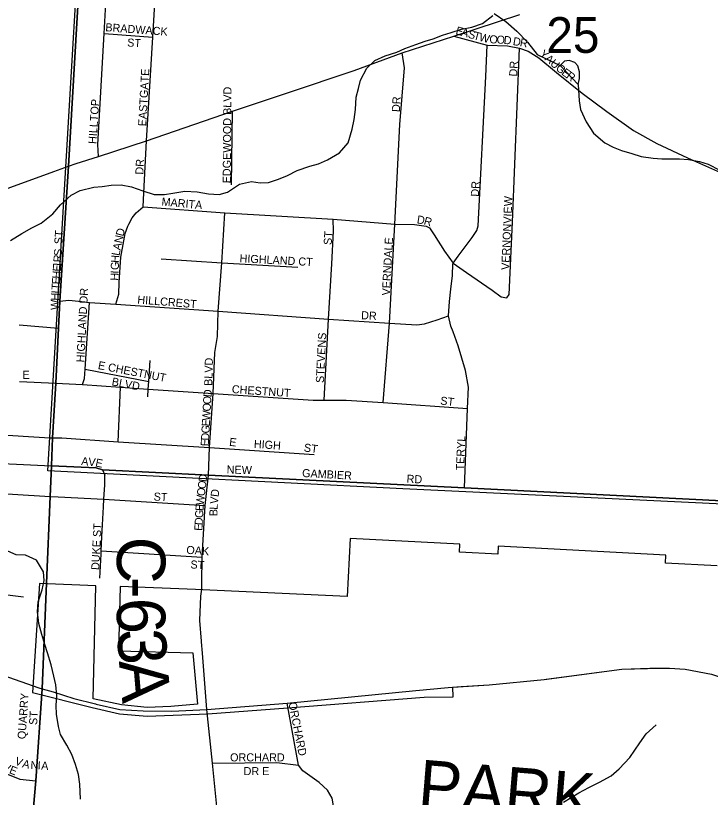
# Model space of a CAD drawing. Extents: x 1759416 to 2214760, y 252598 to 1116833.
# Drawn here: x 1977371 to 1981672, y 869319 to 874156 of the extents above; entities that cross this region are included whole.
import ezdxf

# ---------------------------------------------------------------- set-up
doc = ezdxf.new("R2010")
doc.units = 0
for name, color, linetype in [('GM_X_City_Street', 7, 'Continuous'), ('GM_X_City_Street_Text', 7, 'Continuous'), ('GM_X_Corporation', 7, 'Continuous'), ('GM_X_County_Road', 7, 'Continuous'), ('GM_X_County_Road_Text', 7, 'Continuous'), ('GM_X_Minor_Lake', 7, 'Continuous'), ('GM_X_Minor_River', 7, 'Continuous'), ('GM_X_Section', 7, 'Continuous'), ('GM_X_Section_Text', 7, 'Continuous'), ('GM_X_State_Route', 7, 'Continuous'), ('GM_X_Township', 7, 'Continuous'), ('GM_X_Township_Road_Text', 7, 'Continuous'), ('GM_X_US_Route', 7, 'Continuous')]:
    doc.layers.add(name, color=color, linetype=linetype)

msp = doc.modelspace()

# ---------------------------------------------------------------- linework, layer by layer
at = {"layer": 'GM_X_City_Street'}
for points in [[(1977883, 873285), (1977878.9, 873357.5), (1977919.3, 874044.4), (1977966.1, 874900.7), (1978005.9, 875593.5)], [(1978180.9, 873380.4), (1978219.7, 874022.9), (1978248.1, 874509.8), (1978265.8, 874818.7), (1978265.8, 874849.5), (1978246.6, 874875.1)], [(1977919.3, 874044.4), (1978219.7, 874022.9)], [(1980083.9, 874029.5), (1980290.1, 873973.8), (1980415.7, 873969.1), (1980490.1, 873955.1)], [(1980078.3, 872619.4), (1980078.5, 872624.8), (1980110.8, 872667.6), (1980196.3, 872782.9), (1980226.1, 872825.7), (1980235.2, 872854.2), (1980282.6, 873779.6), (1980290.1, 873973.8)], [(1980426.9, 872430.4), (1980447.7, 872877.6), (1980490.1, 873955.1)], [(1980490.1, 873955.1), (1980542.9, 873936.5), (1980609.6, 873894.6), (1980719.7, 873804.6), (1980877.9, 873675.8), (1981031.5, 873562.6), (1981195.9, 873444.6), (1981340.2, 873365.5), (1981530.3, 873275.4), (1981716.3, 873192.9), (1981913, 873117.8), (1982134.7, 873057.1), (1982427.2, 872997.4), (1982786.1, 872931.2), (1983154.2, 872866.4), (1983249.7, 872854.1), (1983411.4, 872851), (1984508.3, 872822.4), (1985169.3, 872863.1), (1985888.8, 872856.3)], [(1979647, 871762.4), (1979684.9, 872253.6), (1979718.7, 872865.9), (1979749.8, 873483), (1979778.4, 873832.3), (1979763.3, 873925.6)], [(1978707.4, 873109.6), (1978714.1, 873565.7)], [(1977990.8, 872370.2), (1978009.5, 872431.9), (1978011.3, 872504.9), (1978022.5, 872660.8), (1978041.3, 872762.8), (1978049.4, 872808.5), (1978065.4, 872852.7), (1978070.8, 872866.2), (1978092.3, 872905.1), (1978117.8, 872936), (1978160.7, 872973.5), (1978165, 873060.1), (1978180.9, 873380.4)], [(1978160.7, 872973.5), (1978665.3, 872936), (1979337.2, 872895.9), (1979718.7, 872865.9), (1979840, 872863.3), (1979911.3, 872852.9), (1979932, 872842.5), (1979961.8, 872799.8), (1980026.6, 872697.4), (1980078.5, 872624.8), (1980162.6, 872566.5), (1980320.7, 872456.4), (1980376.4, 872414.9), (1980412.7, 872409.7), (1980426.9, 872430.4)], [(1978570.1, 871483.2), (1978592.7, 871816.9), (1978603.2, 872070.8), (1978619.4, 872170.3), (1978624.7, 872327.2), (1978647.2, 872626.5), (1978665.3, 872936)], [(1979280.6, 871777.3), (1979308.6, 872277.1), (1979327.9, 872619), (1979339.1, 872822.9), (1979337.2, 872895.9)], [(1977617, 871848.4), (1977618.8, 871881.1), (1977637, 872221.2), (1977644.7, 872388.6), (1977673.5, 872806.1)], [(1978272.1, 872651.7), (1978647.2, 872626.5), (1979116.9, 872599.2)], [(1980149.3, 871233.5), (1980168.2, 871724.1), (1980174.6, 871856.1), (1980155.5, 871960.4), (1980110.8, 872113.6), (1980078.8, 872198.7), (1980065.5, 872233.4), (1980051.2, 872298.2), (1980057.7, 872386.3), (1980065.5, 872464.1), (1980075.9, 872548.4), (1980078.3, 872619.4)], [(1977644.7, 872388.6), (1977700.4, 872394.4), (1977798.3, 872384)], [(1977784.6, 871872.8), (1977797.1, 871910.2), (1977800.7, 871967.4), (1977827.4, 872380.9)], [(1977798.3, 872384), (1977827.4, 872380.9), (1977990.8, 872370.2), (1978624.7, 872327.2), (1979308.6, 872277.1), (1979684.9, 872253.6), (1979853.7, 872242.8)], [(1979853.7, 872242.8), (1979855, 872242.7), (1979902, 872248.2), (1979979.8, 872273.5), (1980051.2, 872298.2)], [(1977392.1, 872242.2), (1977637, 872221.2)], [(1978188.7, 871797.8), (1978192, 871844.7), (1978195.3, 871892.5), (1978204.3, 872022.6)], [(1977800.7, 871967.4), (1978195.3, 871892.5)], [(1977393.9, 871892.4), (1977618.8, 871881.1), (1977784.6, 871872.8), (1978020.1, 871856.7), (1978192, 871844.7), (1978592.7, 871816.9), (1979212.7, 871777.3), (1979280.6, 871777.3), (1979416.3, 871775.4), (1979647, 871762.4), (1980168.2, 871724.1)], [(1977591.8, 871369.4), (1977599.9, 871542.5), (1977617, 871848.4)], [(1978005.9, 871519.4), (1978020.1, 871856.7)], [(1977219.2, 871566.5), (1977582.9, 871543.6)], [(1977582.9, 871543.6), (1977599.9, 871542.5), (1977656.2, 871542.5), (1978005.9, 871519.4), (1978570.1, 871483.2)], [(1976619.5, 871518), (1976724.4, 871498.3), (1976774.7, 871474.1), (1976921.6, 871431.8), (1976994.1, 871409.7), (1977068.6, 871395.6), (1977591.8, 871369.4), (1977869, 871356.9), (1977908.6, 871345.6), (1977923.7, 871311.6)], [(1978523.1, 870646.6), (1978526.1, 870804.9), (1978544.2, 871124.9), (1978564.3, 871312.8), (1978570.1, 871483.2)], [(1978570.1, 871483.2), (1979218.4, 871439.8)], [(1977914, 871116.1), (1977916.5, 871163.1), (1977923.7, 871253.2), (1977923.7, 871311.6)], [(1978564.3, 871312.8), (1980149.3, 871233.5), (1983790.8, 871051.3)], [(1976928.4, 871220.2), (1976948.8, 871218.5), (1977584.2, 871181.1), (1977634.1, 871178.2), (1977916.5, 871163.1), (1978544.2, 871124.9)], [(1977899.7, 870822.5), (1977900.7, 870843.7), (1977904.4, 870930.4), (1977914, 871116.1)], [(1977892.2, 870675.8), (1977899.7, 870822.5)], [(1977900.7, 870843.7), (1978526.1, 870804.9)], [(1976277.6, 870626), (1976567.9, 870618.1), (1976914.7, 870593), (1977235.6, 870582.2), (1977420, 870560)], [(1977468.9, 869117.6), (1977495.1, 869420.8), (1977534.2, 869990.2)], [(1979348.7, 869164), (1979338, 869267.1), (1979330.5, 869314), (1979301.7, 869362.5), (1979250.5, 869411), (1979148.7, 869482.9), (1979121.7, 869517.3), (1979051.4, 869902.1)], [(1978680.1, 868628.4), (1978664.6, 868852.9), (1978623.1, 869200.4), (1978589.8, 869530.7), (1978554.4, 869863)], [(1977087.7, 869535.3), (1977148.1, 869530.7), (1977397.6, 869431.1), (1977495.1, 869420.8)], [(1978589.8, 869530.7), (1978988.5, 869533.8), (1979121.7, 869517.3)]]:
    msp.add_lwpolyline(points, dxfattribs=at)
at = {"layer": 'GM_X_Corporation'}
msp.add_lwpolyline([(1981713.8, 870751.3), (1981394.2, 870768), (1981396.8, 870817.9), (1980358.2, 870872.4), (1980355.6, 870822.5), (1980118.5, 870835), (1980121.1, 870884.9), (1979442, 870920.5), (1979423.2, 870561), (1978484.5, 870605.6), (1978017.3, 870622.8), (1978007.8, 870225), (1978466.9, 870213.1), (1978496.1, 869894.8), (1978330.8, 869881), (1978184.7, 869874.8), (1978026.4, 869891.8), (1977850.6, 869927.4), (1977867.4, 870628.3), (1977518.8, 870641.2), (1977476, 869966.8), (1977843.7, 869875.1), (1978014.5, 869834.7), (1978185.4, 869820.7), (1978561.2, 869834.7), (1979056.4, 869873.4), (1979899.5, 869938.3), (1980080.4, 869941.4), (1980076.8, 870001.1), (1980301.7, 870014.2), (1980642.8, 870048), (1981124, 870112.4), (1981297.7, 870117.2), (1981418.4, 870118.8), (1981515, 870112.4), (1981677.8, 870080.2)], dxfattribs=at)
at = {"layer": 'GM_X_County_Road'}
for points in [[(1978522, 870280.8), (1978521.7, 870284.3), (1978510.4, 870413), (1978517.2, 870564.1), (1978522.4, 870607.3), (1978523.1, 870646.6)], [(1978554.4, 869863), (1978527.3, 870211.6), (1978522, 870280.8)]]:
    msp.add_lwpolyline(points, dxfattribs=at)
at = {"layer": 'GM_X_Minor_Lake'}
for points in [[(1980853.6, 873730.6), (1980861.8, 873766.6), (1980862.1, 873808.6), (1980850.3, 873844.8), (1980832.4, 873864.9), (1980798.4, 873877.2), (1980768.4, 873873.3), (1980742.2, 873847.5)], [(1980742.2, 873847.5), (1980853.6, 873730.6)]]:
    msp.add_lwpolyline(points, dxfattribs=at)
at = {"layer": 'GM_X_Minor_River'}
for points in [[(1977338.1, 872765.4), (1977408.5, 872807.1), (1977470.8, 872842.7), (1977529, 872872.4), (1977601.4, 872930), (1977647.8, 872985.8), (1977714.3, 873045.5), (1977770.5, 873073.2), (1977854.7, 873094.7), (1977906.8, 873098.3), (1977962.9, 873106), (1978025, 873109.6), (1978088.9, 873097.2), (1978158.8, 873070.7), (1978228.8, 873048.2), (1978292.8, 873049.8), (1978342.9, 873057.5), (1978419.1, 873069), (1978495.1, 873066.5), (1978565.1, 873054.1), (1978631.2, 873049.7), (1978681.3, 873063.4), (1978755.7, 873113), (1978831.8, 873128.5), (1978883.9, 873122.2), (1978935.9, 873123.8), (1978998.1, 873143.5), (1979054.3, 873167.2), (1979114.5, 873196.8), (1979192.8, 873224.3), (1979244.9, 873238), (1979301.1, 873263.7), (1979375.5, 873307.3), (1979429.9, 873369.1), (1979454.5, 873453), (1979466.9, 873513.1), (1979475.3, 873575.1), (1979479.8, 873651.2), (1979494.1, 873705.2), (1979506.5, 873757.2), (1979545, 873831.1), (1979595.3, 873878.8), (1979657.5, 873906.5), (1979729.8, 873930), (1979780, 873951.8), (1979848.2, 873977.4), (1979906.4, 873997), (1979956.5, 874012.7), (1980012.7, 874034.4), (1980066.9, 874052.1), (1980131, 874071.7), (1980195.2, 874085.3), (1980261.4, 874106.9), (1980325.8, 874156.6)], [(1980333.2, 874169.5), (1980405.6, 874120), (1980473.3, 874059.5), (1980538.9, 873991), (1980598.5, 873914.5), (1980742.5, 873847.8)], [(1980853.6, 873730.6), (1980858.9, 873628.4), (1980868.6, 873574.2), (1980902.1, 873497.9), (1980947.7, 873429.5), (1981017.4, 873368.9), (1981069.3, 873342.6), (1981121.2, 873322.2), (1981185.2, 873301.8), (1981243.1, 873283.4), (1981317.1, 873272.9), (1981371.1, 873270.5), (1981481.2, 873269.8), (1981537.3, 873265.5), (1981605.2, 873253), (1981657.2, 873236.7), (1981731, 873200.1)], [(1977772.7, 869307.2), (1977767.2, 869399.4), (1977759.6, 869459.5), (1977742, 869521.7), (1977718.4, 869584), (1977686.7, 869642.3), (1977649.1, 869706.6), (1977635.4, 869756.8), (1977623.9, 869833), (1977622.2, 869887.1), (1977626.6, 869949.1), (1977619, 870015.3), (1977607.3, 870069.5), (1977589.8, 870137.7), (1977568.2, 870211.9), (1977550.5, 870264.1), (1977532.9, 870326.3), (1977515.3, 870394.6), (1977505.8, 870466.7), (1977510.2, 870528.8), (1977534.6, 870602.8), (1977547, 870660.8), (1977543.4, 870714.9), (1977499.8, 870785.3), (1977431.9, 870817.8), (1977373.9, 870820.1), (1977304, 870850.6)], [(1980762.6, 869287.9), (1980857.8, 869345.6), (1980920.1, 869379.3), (1980986.4, 869412.9), (1981056.7, 869452.5), (1981107, 869494.2), (1981173.5, 869565.9), (1981236.1, 869655.7), (1981274.5, 869711.5), (1981336.9, 869767.2)]]:
    msp.add_lwpolyline(points, dxfattribs=at)
at = {"layer": 'GM_X_Section'}
msp.add_lwpolyline([(1983297.5, 876521), (1983041.3, 871071.1), (1980762.8, 871180), (1979768.8, 871227.4), (1977569.5, 871339.3), (1977893.7, 876803.2)], close=True, dxfattribs=at)
at = {"layer": 'GM_X_State_Route'}
for points in [[(1972869.6, 871157.2), (1973322.3, 871123.7), (1973630.8, 871099.6), (1973977.1, 871084.7), (1974317.9, 871056.2), (1974634.9, 870951.4), (1974972, 870847.6), (1975249.9, 870755), (1975624.1, 870620.3), (1975663.6, 870608), (1975882.4, 870537.8), (1976011.8, 870498.1), (1976209.2, 870436.6), (1976578.2, 870317.4), (1976616.7, 870304.5), (1976887.8, 870217.1), (1977109.7, 870135.7), (1977212, 870101.6), (1977513.8, 869997.3)], [(1980655, 870049.6), (1981124, 870112.4), (1981283.4, 870116.8)], [(1981283.4, 870116.8), (1981297.7, 870117.2), (1981418.4, 870118.8), (1981515, 870112.4), (1981677.8, 870080.2), (1981849.4, 870025.6), (1982015.3, 869935.8), (1982097.2, 869879.3), (1982122.9, 869863)], [(1980129.8, 870004.2), (1980301.7, 870014.2), (1980642.8, 870048), (1980655, 870049.6)], [(1977513.8, 869997.3), (1977534.2, 869990.2), (1977602.8, 869970.9), (1977731.1, 869930.4), (1977864.6, 869897.1), (1977870.2, 869895.8)], [(1978554.4, 869863), (1978554.4, 869863), (1979051.4, 869902.1), (1979849.2, 869980), (1980048.3, 869999.4), (1980129.8, 870004.2)], [(1977870.2, 869895.8), (1978015.3, 869863), (1978159.7, 869853.9), (1978336.7, 869851.7), (1978554.4, 869863)]]:
    msp.add_lwpolyline(points, dxfattribs=at)
at = {"layer": 'GM_X_Township'}
for points in [[(1983790.8, 871051.3), (1980149.3, 871233.5), (1978564.3, 871312.8), (1977908.6, 871345.6), (1977869, 871356.9), (1977591.8, 871369.4), (1977599.9, 871542.6), (1977618.8, 871881.1), (1977637, 872221.2), (1977644.7, 872388.6), (1977697.3, 873223.6), (1977838.2, 875632.9), (1977979.1, 878190.1), (1978022.2, 878973.2), (1978052.6, 879525.8), (1978080.8, 880037.7), (1978275, 883589.5), (1978647.5, 890098.7)], [(1956242.2, 879260.7), (1964932.8, 878929.4), (1964958.6, 878928.7), (1965060.6, 878925.7), (1965111.4, 878913), (1968980.9, 878660), (1969836.3, 878615.3), (1971368.2, 878535.3), (1971697.9, 878518.1), (1976487.6, 878268), (1977255.6, 878227.9), (1977979.1, 878190.1), (1977838.2, 875632.9), (1977697.3, 873223.6), (1977644.7, 872388.6), (1977637, 872221.2), (1977618.8, 871881.1), (1977599.9, 871542.6), (1977591.8, 871369.4), (1977584.2, 871181.1), (1977562.4, 870644.2), (1977534.2, 869990.2), (1977495.1, 869420.8), (1977468.9, 869117.6)], [(1977468.9, 869117.6), (1977495.1, 869420.8), (1977534.2, 869990.2), (1977562.4, 870644.2), (1977584.2, 871181.1), (1977591.8, 871369.4), (1977869, 871356.9), (1977908.6, 871345.6), (1978564.3, 871312.8), (1980149.3, 871233.5), (1983790.8, 871051.3)]]:
    msp.add_lwpolyline(points, dxfattribs=at)
at = {"layer": 'GM_X_US_Route'}
for points in [[(1979053, 873678.3), (1979466.8, 873815.7), (1979763.3, 873925.6), (1980083.9, 874029.5), (1980491.8, 874162)], [(1977607.9, 873191.4), (1977697.3, 873223.6), (1977744.7, 873240.7), (1977883, 873285), (1978180.9, 873380.4), (1978714.1, 873565.7), (1979053, 873678.3)], [(1977044.2, 872988.4), (1977072.2, 872998.2), (1977607.9, 873191.4)]]:
    msp.add_lwpolyline(points, dxfattribs=at)

# ---------------------------------------------------------------- texts
at = {"layer": 'GM_X_City_Street_Text'}
for s, rotation, p in [('BRADWACK', 355.7633, (1977924.7, 874059.8)), ('E', 344.3136, (1980091.4, 874041.9)), ('A', 344.3098, (1980125.2, 874032.4)), ('S', 344.3136, (1980167.6, 874020.5)), ('T', 344.3136, (1980201.5, 874011)), ('W', 345.8348, (1980236.8, 874001.1)), ('ST', 356.4254, (1978060, 873965.2)), ('O', 356.829, (1980302.6, 873985.5)), ('O', 357.7748, (1980347.4, 873983)), ('D', 354.2851, (1980390.6, 873981.4)), ('D', 349.6502, (1980446.3, 873974.8)), ('R', 349.4997, (1980489.5, 873966.9)), ('Y', 318.5571, (1980609.8, 873912.3)), ('A', 318.5571, (1980642.8, 873883.2)), ('DR', 86.989, (1980475.4, 873778.1)), ('U', 318.5407, (1980675.8, 873854.1)), ('EASTGATE', 86.8218, (1978178.6, 873470.2)), ('G', 321.121, (1980710.6, 873823.3)), ('E', 323.0551, (1980746.4, 873794.6)), ('R', 323.1312, (1980774.6, 873773.4)), ('EDGEWOOD BLVD', 89.5306, (1978702.2, 873117.7)), ('HILLTOP', 86.1237, (1977870.6, 873360.3)), ('DR', 86.989, (1979749.4, 873558.2)), ('DR', 86.989, (1978161, 873170.9)), ('DR', 86.9884, (1980238.4, 873034.5)), ('VERNONVIEW', 87.5869, (1980427, 872581.3)), ('MARITA', 354.8041, (1978272.4, 872981.2)), ('D', 350.7569, (1979852.1, 872871.2)), ('R', 344.0613, (1979894.1, 872864.5)), ('D', 75.757, (1978037.7, 872786.9)), ('ST', 86.1879, (1977659.4, 872739.9)), ('N', 78.0472, (1978028.7, 872744.3)), ('ST', 86.4118, (1979327, 872735.4)), ('A', 78.1113, (1978019.7, 872701.3)), ('VERNDALE', 86.9459, (1979687.8, 872423)), ('S', 86.0888, (1977656.5, 872667.4)), ('L', 79.7831, (1978013.5, 872667)), ('R', 86.0632, (1977653.8, 872627.9)), ('H', 85.8209, (1978010.5, 872624.5)), ('HIGHLAND CT', 356.9866, (1978756.1, 872629.8)), ('E', 86.0623, (1977649.9, 872570.8)), ('I', 86.1025, (1977652.3, 872605.9)), ('G', 88.1575, (1978009.1, 872581.1)), ('H', 86.0857, (1977646.9, 872526.9)), ('H', 88.1637, (1978007, 872515.1)), ('I', 88.1589, (1978008.4, 872559.1)), ('E', 86.0888, (1977644.5, 872491.8)), ('T', 86.0623, (1977642.1, 872456.6)), ('HIGHLAND DR', 87.0179, (1977795.8, 872009.3)), ('H', 86.6104, (1977638, 872390.9)), ('I', 86.1074, (1977640.6, 872434.7)), ('HILLCREST', 355.4255, (1978122.7, 872374.6)), ('W', 89.3443, (1977637.4, 872334.3)), ('DR', 356.989, (1979508.5, 872277.8)), ('STEVENS', 87.186, (1979278.6, 871881.7)), ('E CHESTNUT', 349.0871, (1977877.4, 871969.7)), ('BLVD', 88.4935, (1978587.8, 871863.9)), ('E', 0, (1977413.6, 871908.3)), ('BLVD', 349.2866, (1977962.7, 871868.5)), ('D', 84.3307, (1978582.6, 871792.7)), ('CHESTNUT', 356.0808, (1978707.8, 871820.3)), ('O', 86.8068, (1978580.2, 871749.4)), ('ST', 352.8783, (1979997.5, 871749.8)), ('O', 86.829, (1978577.8, 871705.5)), ('W', 86.8043, (1978574.6, 871648.3)), ('E', 86.8216, (1978572.6, 871613.2)), ('G', 86.8068, (1978570.2, 871569.2)), ('E', 86.802, (1978565.8, 871490.1)), ('D', 86.829, (1978567.7, 871525.3)), ('E', 352.8783, (1978690.7, 871494.6)), ('TERYL', 87.4567, (1980146, 871340.4)), ('HIGH', 356.1833, (1978844.2, 871481.4)), ('ST', 352.4111, (1979152.8, 871459.4)), ('A', 354.1763, (1977775.1, 871375.8)), ('V', 354.1804, (1977818.8, 871371.4)), ('E', 348.39, (1977861.3, 871367.1)), ('NEW', 358.2109, (1978676.7, 871323)), ('GAMBIER', 356.9047, (1979143.3, 871301.1)), ('D', 83.1408, (1978552, 871268.1)), ('RD', 356.9776, (1979790.1, 871265.8)), ('O', 83.1433, (1978546.7, 871224.4)), ('ST', 356.4254, (1978223.8, 871155.8)), ('O', 83.165, (1978541.5, 871180.7)), ('D', 83.2978, (1978626.8, 871175.4)), ('W', 83.8009, (1978535.3, 871124)), ('V', 84.4177, (1978622.6, 871131.9)), ('E', 86.2277, (1978533.1, 871089.4)), ('B', 89.4657, (1978620, 871058.3)), ('L', 86.364, (1978620.4, 871097.2)), ('G', 86.784, (1978530.6, 871045.6)), ('DUKE ST', 87.0365, (1977888.1, 870724.2)), ('E', 86.802, (1978526.2, 870966.6)), ('D', 86.785, (1978528.1, 871001.7)), ('OAK', 356.1879, (1978426.2, 870825.8)), ('ST', 356.4254, (1978451.6, 870735.6)), ('QUARRY', 86.1198, (1977431.9, 869677.1)), ('ORCHARD', 281.1436, (1979059.6, 869903.1)), ('ST', 86.4254, (1977503.2, 869765.3)), ('V', 339.0143, (1977360.8, 869523.3)), ('ORCHARD', 0, (1978698.4, 869541.1)), ('AVE', 337.838, (1977244.5, 869503.7)), ('A', 346.6065, (1977408.8, 869505.4)), ('N', 357.6623, (1977462, 869493.7)), ('I', 356.8517, (1977505.8, 869491.9)), ('A', 356.8068, (1977527.8, 869490.7)), ('DR E', 0, (1978782, 869456))]:
    msp.add_text(s, height=50, rotation=rotation, dxfattribs=at).set_placement(p)
at = {"layer": 'GM_X_County_Road_Text'}
for s, rotation, p in [('C', 268.6377, (1978001.3, 870935.4)), ('-', 269.5633, (1977995.4, 870683.8)), ('6', 271.4066, (1977994.5, 870550)), ('3', 273.0064, (1977999.4, 870356.1)), ('A', 274.7777, (1978009.8, 870161.5))]:
    msp.add_text(s, height=300, rotation=rotation, dxfattribs=at).set_placement(p)
at = {"layer": 'GM_X_Section_Text'}
msp.add_text('25', height=221, rotation=0, dxfattribs=at).set_placement((1980656.4, 873925.4))
at = {"layer": 'GM_X_Township_Road_Text'}
msp.add_text('PARK', height=300, rotation=355.345, dxfattribs=at).set_placement((1979854.9, 869254))

doc.saveas('drawing.dxf')
